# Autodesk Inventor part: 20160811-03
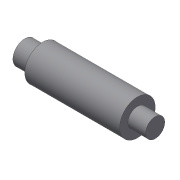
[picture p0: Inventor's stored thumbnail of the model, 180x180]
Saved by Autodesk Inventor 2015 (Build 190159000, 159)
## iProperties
Created: 2016-08
Part Number: 20160811-03
Material: Mosaz, měkká žlutá
Document SubType Name: Modeling
Designer: navara
Density: 8.47 g/cm^3
Appearance: Mosaz – satén
Beppe: 20160811-03.ipt
Author: navara
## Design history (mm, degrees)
sketch "Náčrt1"
  geometry: L1 (0, 0)-(0, 10); L2 (0, 10)-(15, 10); L3 (15, 10)-(15, 15); L4 (15, 15)-(95, 15); L5 (95, 15)-(95, 10); L6 (95, 10)-(110, 10); L7 (110, 10)-(110, 0); L8 (110, 0)-(0, 0)
  constraints: 16 end point, 5 perpendicular, 1 collinear, 1 horizontal, 1 parallel, 1 vertical
  dimensions: "d0" = 20 diameter of L2 L8; "d1" = 30 diameter of L4 L8; "d2" = 15 distance of L1.end L2.end; "d3" = 15 distance of L5.end L6.end (= d2); "d5" = 110 distance of L7.end L1.start
revolve "Rotace1" sketch "Náčrt1" stored, may be unused: angle "d4" = 90 deg
node "Těleso1"
